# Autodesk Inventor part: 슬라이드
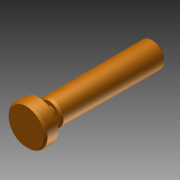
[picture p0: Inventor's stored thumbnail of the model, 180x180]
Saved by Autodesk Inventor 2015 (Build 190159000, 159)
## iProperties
Created: 2025-08
Part Number: 슬라이드
Material: 일반
Document SubType Name: Modeling
Designer: USER
Density: 1 g/cm^3
Appearance: 기본값
Author: USER
Author: jhkim
Creation Date: 2025-08-05
Sending System: Autodesk Inventor 2026
Preprocessor: ST-DEVELOPER v20.1
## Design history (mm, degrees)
node "슬라이드1"
node "솔리드1"
node "기준1"
